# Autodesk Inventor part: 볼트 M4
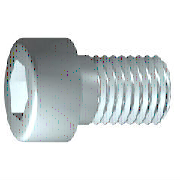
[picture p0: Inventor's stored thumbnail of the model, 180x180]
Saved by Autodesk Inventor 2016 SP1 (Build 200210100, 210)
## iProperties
IsCustomPart: 0
Created: 2016-04
Part Number: 볼트 M4
Material: 강철, 연강
Description: 6각머리 태핑 나사
Document SubType Name: Modeling
Standard: KS B 1003
Designer: mdu
Standards Organization: KS
Language: ko-KR
Size Designation: M 4 x 10
Categories: <MemberInstance><Categories><Category DisplayName="조임쇠" InternalName="e4da775c-781d-43d5-af7c-5136215cf5a6" Mnemonic="FSTN"><Category DisplayName="볼트" InternalN
Density: 7.86 g/cm^3
Mass: 2.0371 g
Surface Area: 3.0572 cm^2
Volume: 0.259174 cm^3
Appearance: 금속 1800F 열
Author: mdu
Revision Number: 1
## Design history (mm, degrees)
sketch "스케치1"
  geometry: L1 (-1, 0)-(10, 0); L2 (10, 0)-(10, 2); L3 (10, 2)-(1.75, 2); L4 (1.75, 2)-(1.32, 2); L5 (1.32, 2)-(0, 2); L6 (0, 2)-(0, 3.5); L7 (0, 3.5)-(-4, 3.5); L8 (-4, 3.5)-(-4, 1.732); L9 (-4, 1.732)-(-2, 1.732); L10 (-2, 1.732)-(-1, 0); L11 (-6.8, 0)-(12.8, 0) reference; L12 (0, -0.7)-(0, 4.2) reference; L13 (1.75, 2)-(0, 2)
  constraints: 22 end point, 6 parallel, 2 collinear, 2 perpendicular, 1 horizontal, 1 point on line
  dimensions: "d1" = 8.25 distance from line of L3.end L2 (= GEL); "d2" = 0.42952 distance of L4.end L3.end (computed from GAL); "d3" = 4 distance between parallel lines of L8 L6 (= KOH); "d4" = 2 distance of L8.end L9.end (= INTI); "d5" = 60 deg angle of L10 L1; "d6" = 4 diameter of L3 L1 (= GD); "d7" = 4 diameter of L5 L1 (= BDM); "d8" = 3.4641 diameter of L9 L1 (= 1.1547 x SW); "d9" = 7 diameter of L7 L1 (= KOD); "d26" = 10 distance between parallel lines of L12 L2 (= NLG)
revolve "본체" sketch "스케치1" stored, may be unused: angle "d10" = 90 deg
sketch "스케치2"
  geometry: L1 (0, -4.9)-(0, 4.9) reference; L2 (-4.9, 0)-(4.9, 0) reference; L3 (1.732, 0)-(0.866, -1.5); L4 (0.866, -1.5)-(-0.866, -1.5); L5 (-0.866, -1.5)-(-1.732, 0); L6 (-1.732, 0)-(-0.866, 1.5); L7 (-0.866, 1.5)-(0.866, 1.5); L8 (0.866, 1.5)-(1.732, 0); 2 further points
  constraints: 12 end point, 1 coincident, 1 horizontal alignment, 1 point on line, 12 other
extrude "슬롯" join sketch "스케치2" stored distance "d11" = 10; taper "d12" = 0 deg
workplane "Work Plane1"
fillet "Fillet2" dims "d30" = 0.1 (= R)
body "Solid1"
fillet "모깎기1" dims "d17" = 0.4 (= RR)
feature "스레드" dims "d13" = 8.25 (= GEL), "d14" = 0
chamfer "모따기1" distance "d15" = 0.42941 (= -0.5 x SPD + 0.5 x GD); stored, may be unused: second distance "d16" = 0.42941 (= GUL), angle "d27" = 45 deg
other parameters: "GD" = 4 (= NND) [user parameter; used in 2 equation terms], "NLG" = 10 [user parameter; used in 1 equation term], "GEL" = 8.25 [user parameter; used in 2 equation terms], "KOD" = 7 [user parameter; used in 1 equation term], "KOH" = 4 [user parameter; used in 1 equation term], "INTI" = 2 [user parameter; used in 1 equation term], "GAL" = 0.42941 (= 0.61345 x PTC) [user parameter; used in 1 equation term], "GUL" = 0.42941 (= 0.61345 x PTC) [user parameter; used in 1 equation term], "BDM" = 4 (= NND) [user parameter; used in 1 equation term], "SW" = 3 [user parameter; used in 2 equation terms], "RR" = 0.4 [user parameter; used in 1 equation term], "SPD" = 3.14117 (= NND - 1.2269 x PTC) [user parameter; used in 1 equation term], "d19" = 0, "d28" = 0, "d29" = 0, "R" = 0.1 [user parameter; used in 1 equation term], "PHH" = 0.2 [user parameter], "GD1" = 3.14117 (= THREADDIA - 1.2269 x PTC) [user parameter], "THREADDIA" = 4 [user parameter; used in 1 equation term], "FAWI" = 45 deg [user parameter], "TPU" = 14.28571 (computed from PTC) [user parameter], "PTC" = 0.7 [user parameter; used in 5 equation terms], "NND" = 4 [user parameter; used in 3 equation terms], "TOA" = 30 deg [user parameter], "E0" = 3.465 (= 1.155 x SW) [user parameter]
